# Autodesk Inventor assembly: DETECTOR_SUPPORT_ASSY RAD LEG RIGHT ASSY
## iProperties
Shininess: 64.0
Length Units: 11272
Angle Units: 11279
Time Units: 11290
Mass Units: 11286
Length Display Precision: 3
Angle Display Precision: 2
Compacted: True
Part Number: DETECTOR_SUPPORT_ASSY RAD LEG RIGHT ASSY
Document SubType Name: Assembly
Created: 2004-08
Designer: John Blackburn
Manufacturer: Standard
Standards Organization: Custom
Density: 0.0
Volumn: 0.0
Area: 0.0
PropertySet Name: Model Information
Control State: 0
Master: False
Checked Out: False
Author: John Blackburn
